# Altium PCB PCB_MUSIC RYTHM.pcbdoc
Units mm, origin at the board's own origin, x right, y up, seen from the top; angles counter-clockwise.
Board outline 74.7 x 53.72 mm, 2 copper layers (Top Layer, Bottom Layer); 26 components, 18 nets, 59 pads, 0 vias.
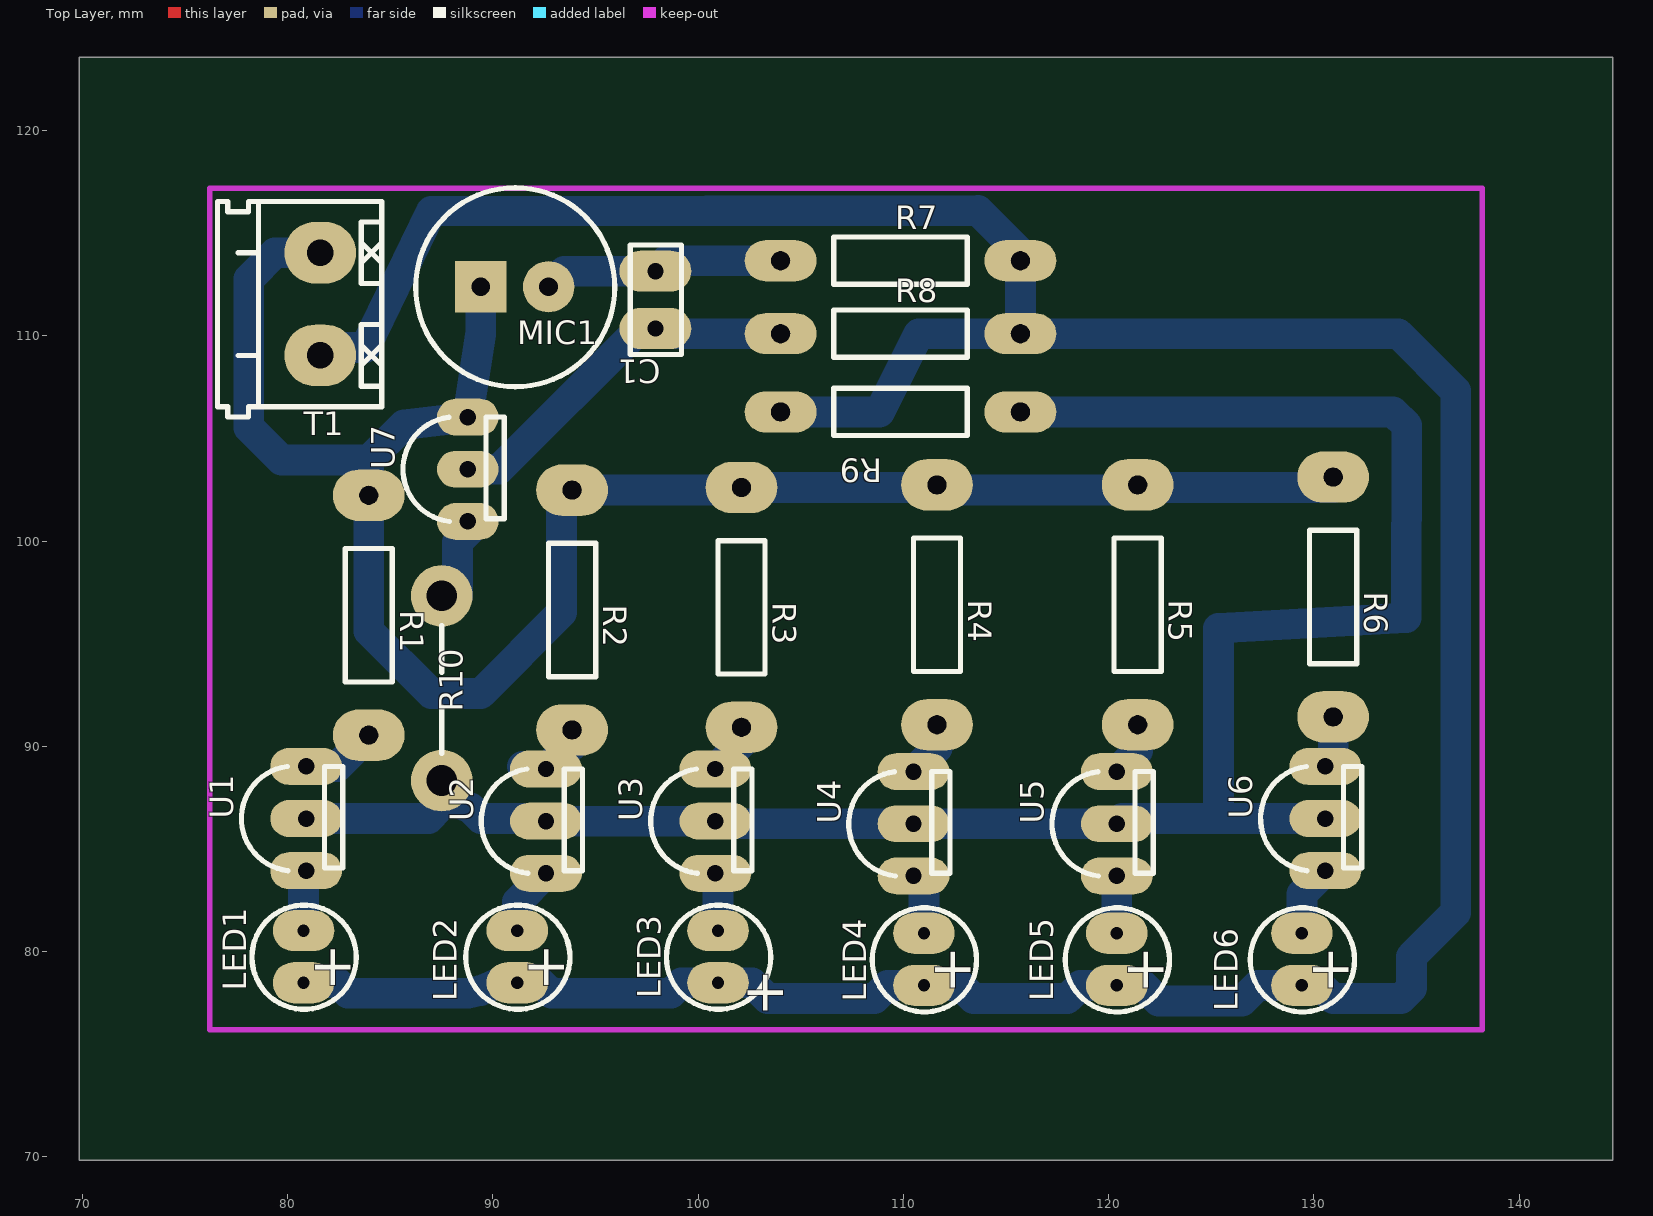
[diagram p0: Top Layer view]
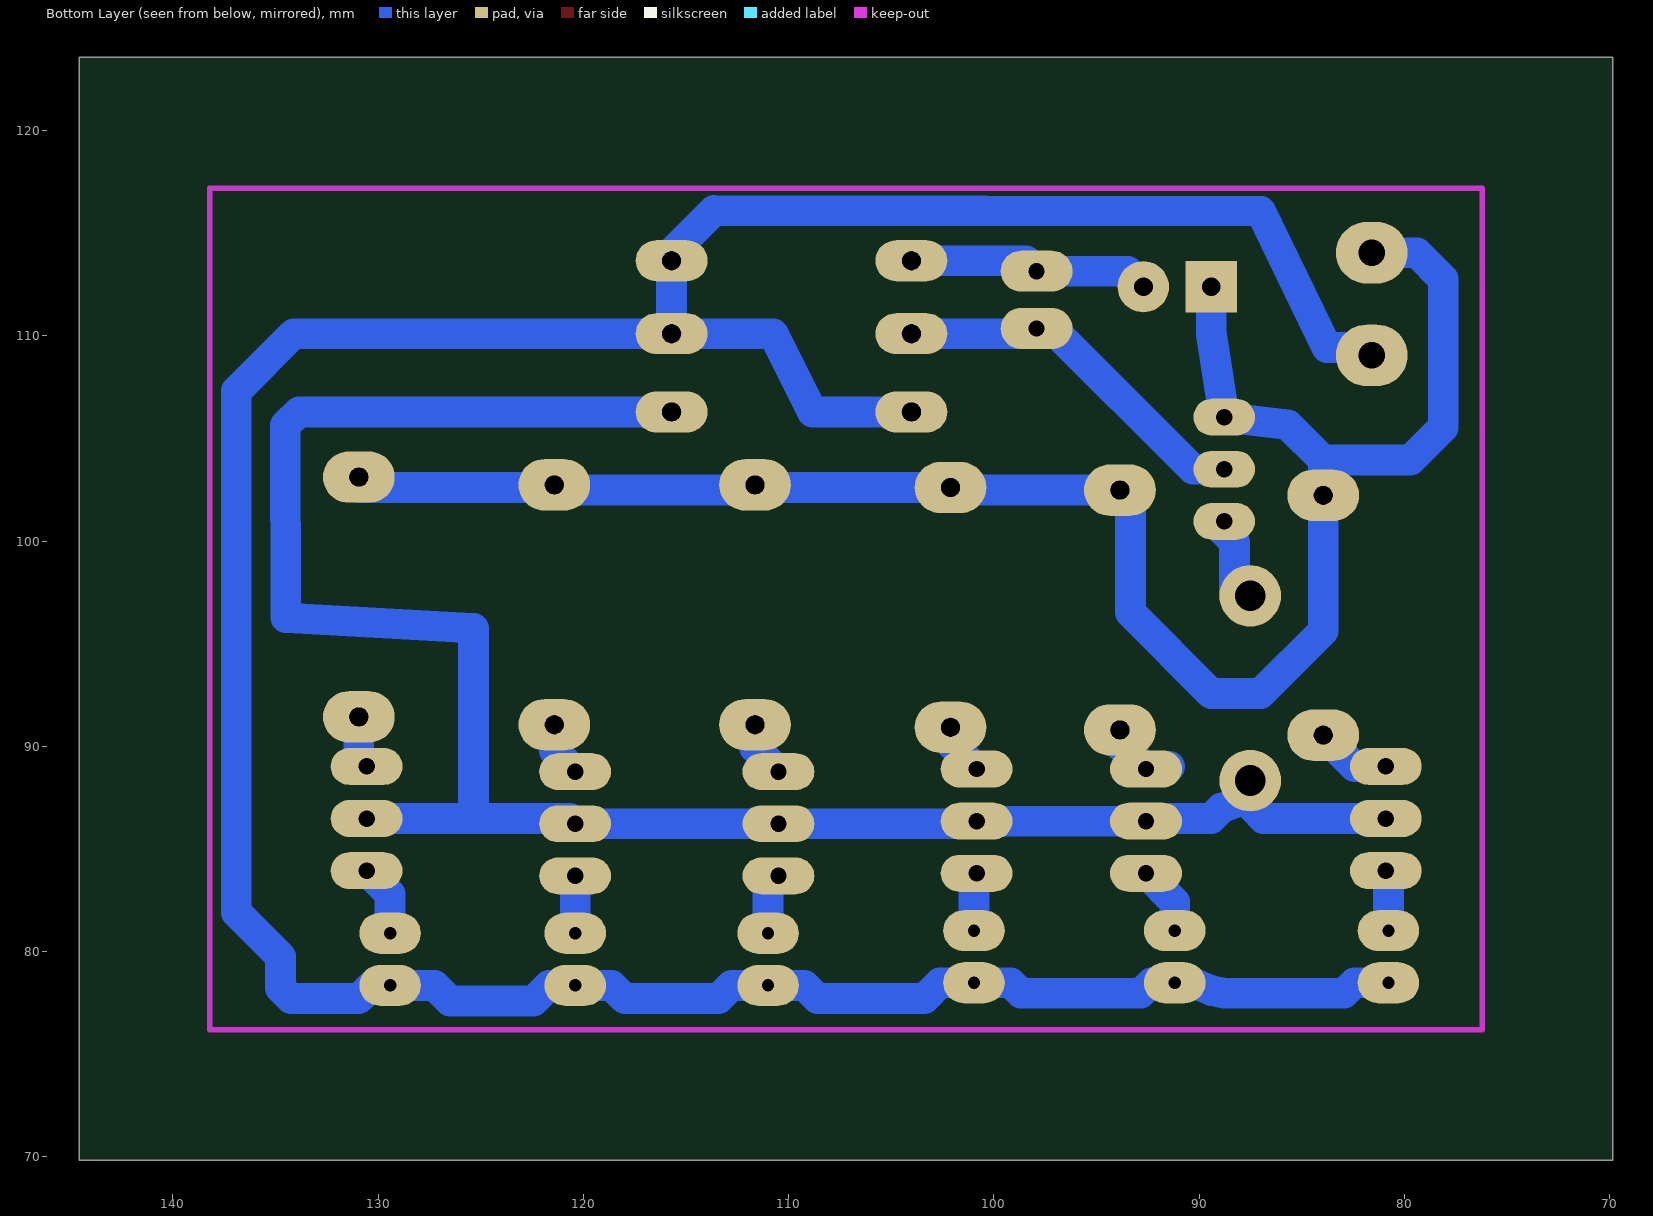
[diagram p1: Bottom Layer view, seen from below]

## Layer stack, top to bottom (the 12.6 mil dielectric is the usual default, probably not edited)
Top Layer: signal copper (thickness not stored)
Dielectric: dielectric 0.32, FR-4, Dk 4.8
Bottom Layer: signal copper (thickness not stored)

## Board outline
144.55,69.85 69.85,69.85 69.85,123.571 144.55,123.571

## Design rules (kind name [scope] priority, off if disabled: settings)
BoardOutlineClearance Default [All] p0: genericclearance=0.254 ignorepadtopadclearanceinfootprint=FALSE except(0: Region-CutoutEdge Arc-SplitContinuation Track-SplitContinuation SMDPad-SplitContinuation THPad-SplitContinuation Via-SplitContinuation Fill-SplitContinuation Poly-SplitContinuation Region-SplitContinuation Text-SplitContinuation; 0.5: Track-OutlineEdge SMDPad-OutlineEdge THPad-OutlineEdge Via-OutlineEdge Fill-OutlineEdge Region-OutlineEdge Poly-OutlineEdge Text-OutlineEdge Sheet-OutlineEdge Hole-OutlineEdge Track-CutoutEdge SMDPad-CutoutEdge THPad-CutoutEdge Via-CutoutEdge Fill-CutoutEdge Poly-CutoutEdge Text-CutoutEdge Sheet-CutoutEdge Hole-CutoutEdge)
Clearance Default [All] p1: gap=0.178 ignorepadtopadclearanceinfootprint=FALSE except(0: Region-Region; 0.5: Track-Track SMDPad-Track THPad-Track Via-Track Fill-Track Region-Track Poly-Track Text-Track Sheet-Track Hole-Track Track-SMDPad SMDPad-SMDPad THPad-SMDPad Via-SMDPad Fill-SMDPad Region-SMDPad Poly-SMDPad Text-SMDPad Sheet-SMDPad Hole-SMDPad Track-THPad SMDPad-THPad THPad-THPad Via-THPad Fill-THPad Region-THPad Poly-THPad Text-THPad Sheet-THPad Hole-THPad Track-Via SMDPad-Via THPad-Via Via-Via Fill-Via Region-Via Poly-Via Text-Via Sheet-Via Hole-Via Track-Fill SMDPad-Fill THPad-Fill Via-Fill Fill-Fill Region-Fill Poly-Fill Text-Fill Sheet-Fill Hole-Fill Track-Region SMDPad-Region THPad-Region Via-Region Fill-Region Poly-Region Text-Region Sheet-Region Hole-Region Track-Poly SMDPad-Poly THPad-Poly Via-Poly Fill-Poly Region-Poly Poly-Poly Text-Poly Sheet-Poly Hole-Poly Track-Text SMDPad-Text THPad-Text Via-Text Fill-Text Region-Text Poly-Text Text-Text Sheet-Text Hole-Text Track-Sheet SMDPad-Sheet THPad-Sheet Via-Sheet Fill-Sheet Region-Sheet Poly-Sheet Text-Sheet Sheet-Sheet Hole-Sheet Track-Hole SMDPad-Hole THPad-Hole Via-Hole Fill-Hole Region-Hole Poly-Hole Text-Hole Sheet-Hole Hole-Hole)
PasteMaskExpansion Common [All] p1: expansion=0
PlaneConnect Default [All] p1: planeconnectstyle=Relief reliefexpansion=0.508 reliefentries=4 reliefconductorwidth=0 reliefairgap=0.025
PolygonConnect Default [All] p1: connectstyle=Relief reliefentries=4 reliefconductorwidth=0 polygonreliefangle="90 Angle" airgapwidth=10
RoutingVias Default [All] p1: viastyle="Through Hole" holewidth=12.008000000000001 minholewidth=12.008000000000001 maxholewidth=2362 width=24.016000000000002 minwidth=24.016000000000002 maxwidth=3938
SolderMaskExpansion Common [All] p1: useseparateexpansions=TRUE expansion=2 expansionbottom=2
Width Default [All] p1: maxlimit=1000 minlimit=59 preferedwidth=59

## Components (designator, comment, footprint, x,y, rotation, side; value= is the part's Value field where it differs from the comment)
C1 "100nF" "CERAMIC - 104" 97.917,113.157 r180 top
LED1 "LED_5MM COPY COPY" LED-5MM-5MM 83.312,81.026 r90 top
LED2 "LED_5MM COPY COPY" LED-5MM-5MM 93.726,81.026 r90 top
LED3 "LED_5MM COPY COPY" LED-5MM-5MM 103.505,81.026 r90 top
LED4 "LED_5MM COPY COPY" LED-5MM-5MM 113.538,80.899 r90 top
LED5 "LED_5MM COPY COPY" LED-5MM-5MM 122.936,80.899 r90 top
LED6 "LED_5MM COPY COPY" LED-5MM-5MM 131.953,80.899 r90 top
MIC1 "Microphone" MICROPHONE 91.059,112.395 r0 top
R1 "1K" "AXIAL-6.5X2.3(1/4W) RESISTOR 1/4W"#1 83.947,96.393 r270 top
R2 "1K" "AXIAL-6.5X2.3(1/4W) RESISTOR 1/4W"#1 93.853,96.647 r270 top
R3 "1K" "AXIAL-6.5X2.3(1/4W) RESISTOR 1/4W"#1 102.108,96.774 r270 top
R4 "1K" "AXIAL-6.5X2.3(1/4W) RESISTOR 1/4W"#1 111.633,96.901 r270 top
R5 "1K" "AXIAL-6.5X2.3(1/4W) RESISTOR 1/4W"#1 121.412,96.901 r270 top
R6 "1K" "AXIAL-6.5X2.3(1/4W) RESISTOR 1/4W"#1 130.937,97.282 r270 top
R7 "10K" "AXIAL-6.5X2.3(1/4W) RESISTOR 1/4W"#2 109.855,113.665 r0 top
R8 "1M" "AXIAL-6.5X2.3(1/4W) RESISTOR 1/4W"#2 109.855,110.109 r0 top
R9 "10K" "AXIAL-6.5X2.3(1/4W) RESISTOR 1/4W"#2 109.855,106.299 r180 top
R10 "1.5MM JUMPER WIRE" "1.5MM JUMPER WIRE" 87.503,92.837 r90 top
T1 "SCREW TERMINAL COPY" "M02 SCREW TERMINAL 5MM 10X8MM" 76.581,106.553 r0 top
U1 "BC547" "TRANS NPN"#1 80.137,86.487 r90 top
U2 "BC547" "TRANS NPN"#1 91.821,86.36 r90 top
U3 "BC547" "TRANS NPN"#1 100.076,86.36 r90 top
U4 "BC547" "TRANS NPN"#1 109.728,86.233 r90 top
U5 "BC547" "TRANS NPN"#1 119.634,86.233 r90 top
U6 "BC547" "TRANS NPN"#1 129.794,86.487 r90 top
U7 "BC547" "TRANS NPN"#2 88.011,103.505 r90 top

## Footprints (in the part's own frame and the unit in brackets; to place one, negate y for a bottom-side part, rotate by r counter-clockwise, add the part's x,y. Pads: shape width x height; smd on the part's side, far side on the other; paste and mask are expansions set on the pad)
"1.5MM JUMPER WIRE" [mm]
  round 3 hole 1.5: 1(4.5,0) 2(-4.5,0)
  silkscreen extent -3.17,0 3.05,0
"AXIAL-6.5X2.3(1/4W) RESISTOR 1/4W"#1 [mm]
  oval 2.5x3.5 hole 0.914 slot 0.919 at 90 deg: 1(-5.842,0) 2(5.842,0)
  silkscreen extent -3.25,-1.15 3.25,1.15
"AXIAL-6.5X2.3(1/4W) RESISTOR 1/4W"#2 [mm]
  oval 3.5x2 hole 0.914 slot 0.919 at 0 deg: 1(-5.842,0) 2(5.842,0)
  silkscreen extent -3.25,-1.15 3.25,1.15
"CERAMIC - 104" [mm]
  oval 3.5x2 hole 0.8: 1(0,0) 2(0,2.794)
  silkscreen extent -1.27,-1.28 1.23,4.06
LED-5MM-5MM [mm]
  oval 2x3 hole 0.6: 1(-2.54,2.54) 2(0,2.54)
  silkscreen extent -3.83,-0.02 1.24,5.06
"M02 SCREW TERMINAL 5MM 10X8MM" [mm]
  oval 3.5x3 hole 1.3: 1(5,7.5) 2(5,2.5)
  silkscreen extent 0,-0.5 8,10
MICROPHONE [mm]
  round 2.5 hole 0.914: 1(1.651,0)
  rect 2.5x2.5 hole 0.914: 2(-1.651,0)
  silkscreen extent -4.83,-4.87 4.87,4.83
"TRANS NPN"#1 [mm]
  oval 1.8x3.5 hole 0.8: 1(-2.54,-0.762) 2(0,-0.762) 3(2.54,-0.762)
  silkscreen extent -2.54,-2.54 2.54,2.39
"TRANS NPN"#2 [mm]
  oval 1.8x3 hole 0.8: 1(-2.54,-0.762) 2(0,-0.762) 3(2.54,-0.762)
  silkscreen extent -2.54,-2.54 2.54,2.39

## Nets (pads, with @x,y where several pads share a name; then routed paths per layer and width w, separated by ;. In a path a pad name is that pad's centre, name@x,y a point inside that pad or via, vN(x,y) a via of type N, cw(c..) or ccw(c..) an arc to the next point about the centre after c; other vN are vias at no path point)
C1_1: C1.1 MIC1.1 R7.1 | length 11.8
  Bottom Layer w1.5: MIC1.1 93.472,113.157 C1.1 98.425,113.665 R7.1
GND: MIC1.2 R1.1 R2.1 R3.1 R4.1 R5.1 R6.1 T1.1 U7.3 | length 93.5
  Bottom Layer w1.5: T1.1@81.582,114.054 79.383,114.054 78.105,112.776 78.105,105.537 79.692,103.95 83.947,103.95 ; MIC1.2 89.408,110.132 U7.3 85.661,105.664 83.947,103.95 ; R2.1@93.853,102.235 93.345,101.727 93.345,96.52 89.408,92.583 86.995,92.583 83.947,95.631 R1.1 83.947,103.95 ; R2.1@93.853,102.552 R2.1 102.108,102.489 R3.1@102.108,102.425 ; R3.1@102.108,102.552 102.171,102.616 R4.1@111.633,102.616 ; R4.1@111.633,102.489 R5.1@121.412,102.489 ; R5.1 121.539,102.616 R6.1@130.937,102.616
LED1_2: LED1.2 U1.1 | length 3
  Bottom Layer w1.5: LED1.2 80.772,83.82 U1.1
LED2_2: LED2.2 U2.1 | length 3.4
  Bottom Layer w1.5: LED2.2 91.186,82.423 U2.1
LED3_2: LED3.2 U3.1 | length 2.8
  Bottom Layer w1.5: U3.1 100.965,83.693 LED3.2
LED4_2: LED4.2 U4.1 | length 3
  Bottom Layer w1.5: U4.1 110.998,83.185 LED4.2
LED5_2: LED5.2 U5.1 | length 2.8
  Bottom Layer w1.5: LED5.2 U5.1
LED6_2: LED6.2 U6.1 | length 3.5
  Bottom Layer w1.5: LED6.2 129.413,82.804 U6.1
R1_2: R1.2 U1.3 | length 3.7
  Bottom Layer w1.5: U1.3 82.423,89.027 R1.2
R2_2: R2.2 U2.3 | length 3.4
  Bottom Layer w1.5: U2.3@91.44,89.027 92.456,89.027 U2.3 93.726,90.043 93.853,90.043 R2.2@93.853,90.551
R3_2: R3.2 U3.3 | length 2.1
  Bottom Layer w1.5: U3.3 102.108,90.17 R3.2@102.108,90.424
R4_2: R4.2 U4.3 | length 2.3
  Bottom Layer w1.5: U4.3 111.633,89.916 R4.2@111.633,90.551
R5_2: R5.2 U5.3 | length 2.2
  Bottom Layer w1.5: U5.3 121.412,89.789 R5.2@121.412,90.551
R6_2: R6.2 U6.3 | length 2.8
  Bottom Layer w1.5: U6.3 130.937,89.027 R6.2
S$2542: R10.1 | length 3.5
  Bottom Layer w1.5: R10.1@88.265,97.337 88.265,99.949 88.9,100.584
U7_1: R9.1 U1.2 U2.2 U3.2 U4.2 U5.2 U6.2 U7.1 | length 100.7
  Bottom Layer w1.5: U1.2 86.872,86.487 87.757,87.448 88.9,86.995 89.408,86.487 91.44,86.487 91.567,86.36 U3.2 100.965,86.233 U4.2 U5.2 120.65,86.487 128.54,86.487 U6.2 ; R9.1 133.858,106.299 134.526,105.631 134.493,96.266 125.349,95.758 125.349,86.487 128.539,86.487
U7_2: C1.2 R8.1 U7.2 | length 18.2
  Bottom Layer w1.5: U7.2 90.297,103.505 97.155,110.363 C1.2 98.171,110.109 R8.1
VCC: LED1.1 LED2.1 LED3.1 LED4.1 LED5.1 LED6.1 R7.2 R8.2 R9.2 T1.2 | length 166
  Bottom Layer w1.5: LED1.1 82.423,78.486 82.931,77.978 88.773,77.978 89.408,78.105 90.297,78.486 LED2.1 92.329,78.486 92.837,77.978 98.679,77.978 99.187,78.486 LED3.1 102.616,78.486 103.378,77.724 108.585,77.724 109.22,78.359 LED4.1 112.776,78.359 113.411,77.724 117.983,77.724 118.618,78.359 LED5.1 121.666,78.359 122.428,77.597 126.492,77.597 127.254,78.359 LED6.1 130.302,78.359 130.937,77.724 134.239,77.724 134.747,78.232 134.747,79.756 136.906,81.915 136.906,107.315 134.112,110.109 R8.2 ; T1.2@81.582,109.433 83.779,109.433 86.995,116.078 113.632,116.111 R7.2@115.697,114.046 ; R9.2 108.839,106.299 110.744,110.109 R8.2 ; R7.2 R8.2
pads on no net: R10.2

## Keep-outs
Board Outline Layer:
  lines w0.254: 76.2,76.2 138.2,76.2 138.2,117.2 76.2,117.2 76.2,76.2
